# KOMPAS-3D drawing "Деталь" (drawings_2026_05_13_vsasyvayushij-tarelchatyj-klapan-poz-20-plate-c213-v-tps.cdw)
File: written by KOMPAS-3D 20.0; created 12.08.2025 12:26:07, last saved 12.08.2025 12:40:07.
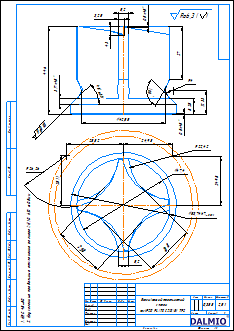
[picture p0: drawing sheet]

Sheet 1: A3, portrait

Document properties: Автор: VLAD; Знак неуказанной шероховатости: 5; Параметр неуказанной шероховатости: Ra6,3; Масса: 0.388; Полное имя файла: Всасывающий тарельчатый клапан.m3d

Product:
- Part/product: Деталь
    Масса: 0.388352

Title block, sheet 1: Наименование: Всасывающий тарельчатый / клапан / поз.№20, PLATE C213 (В) TPS; Масса: 0,388; Количество листов документа: 1; Форматы листов документа: A3; stored path: C:\Users\VLAD\Desktop\Всасывающий тарельчатый клапан  поз.№20, PLATE C213 (В) TPS.cdw

Views: Вид 1, Спереди, Проекционный вид 2
Referenced files in C:\Users\VLAD\Desktop\: Всасывающий тарельчатый клапан.m3d
Referenced files in D:\Библиотека\: Логотип.jpg
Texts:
  Ra0,63
  1. HRC 48-50
  2. Неуказанные предельные отклонения размеров Н10, h10, ±0,5мм
  Ra6,3
  Ra6,3 ( )
Dimensions and other numbers on the sheet: 0,5; 8,25; 27; 3,25; 5,2; 3,17; 44,6; 105; 4; 12,33; 4,3; 42,55; 53,74; 26,26; 47,4; 28,82; 25,11; 22,42; 25,8; 24,98; 2,5:1; 1; 0,388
